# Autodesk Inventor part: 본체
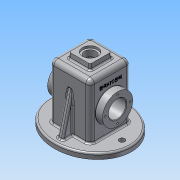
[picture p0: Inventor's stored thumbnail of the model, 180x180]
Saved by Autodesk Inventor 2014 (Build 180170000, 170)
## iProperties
Created: 2017-07
Part Number: 본체
Material: 알루미늄 6061
Document SubType Name: Modeling
Designer: 학생용
Density: 2.71 g/cm^3
Appearance: 알루미늄 - 평지
Mass: 894.559 g
Surface Area: 979.096 cm^2
Volume: 330.096 cm^3
Author: 학생용
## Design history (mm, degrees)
sketch "스케치2"
  geometry: L1 (-75, -65)-(75, -65); L2 (75, -65)-(75, 65); L3 (75, 65)-(-75, 65); L4 (-75, 65)-(-75, -65); L5 (-75, -65)-(75, 65); L6 (75, -65)-(-75, 65); 4 further points; 1 other entity
  constraints: 12 end point, 6 midpoint, 2 horizontal, 2 parallel, 1 perpendicular, 4 other
  dimensions: "d1" = 150 distance of L2.end L3.end; "d2" = 130 distance of L1.end L2.end
extrude "돌출1" new body sketch "스케치2" distance "d3" = 10; taper "d4" = 0 deg
sketch "스케치3"
  geometry: L1 (37, 10)-(-37, 10); L2 (-37, 10)-(-37, 110); L3 (-37, 110)-(37, 110); L4 (37, 110)-(37, 10); L5 (75, 10)-(-75, 10) reference; 2 further points
  constraints: 8 end point, 2 parallel, 1 collinear, 1 horizontal, 1 midpoint, 1 perpendicular, 1 vertical alignment
  dimensions: "d5" = 74 distance of L2.end L3.end; "d6" = 110 distance from line of L3 point (0, 0)
extrude "돌출2" join sketch "스케치3" stored distance "d7" = 74; taper "d8" = 0 deg
fillet "모깎기1" dims "d9" = 8
fillet "모깎기2" dims "d10" = 8
feature "쉘1" dims "d11" = 10, "d12" = 5
sketch "스케치4"
  geometry: L1 (-75, 0)-(-75, 10) reference; L2 (-75, 10)-(-37, 10) reference; L3 (-37, 10)-(-37, 102) reference; L4 (-29, 110)-(29, 110) reference; L5 (37, 102)-(37, 10) reference; L6 (37, 10)-(75, 10) reference; L7 (75, 10)-(75, 0) reference; L8 (75, 0)-(32, 0) reference; L9 (32, 0)-(32, 102) reference; L10 (29, 105)-(-29, 105) reference; L11 (-32, 102)-(-32, 0) reference; L12 (-32, 0)-(-75, 0) reference; L13 (32, 82.5)-(25, 75.5); L14 (25, 75.5)-(25, 55); L15 (25, 55)-(32, 55); L16 (32, 82.5)-(32, 55); L17 (-29, 0)-(29, 0) reference; A1 r 8 centre (-29, 102) between (-29, 110) and (-37, 102) reference; A2 r 8 centre (29, 102) between (37, 102) and (29, 110) reference; A3 r 3 centre (29, 102) between (32, 102) and (29, 105) reference; A4 r 3 centre (-29, 102) between (-29, 105) and (-32, 102) reference; 1 further point
  constraints: 8 end point, 2 perpendicular, 2 point on line, 1 collinear
  dimensions: "d13" = 55 distance between parallel lines of L17 L15; "d14" = 55 diameter of L13.start L15; "d15" = 7 distance between parallel lines of L14 L16; "d16" = 135 deg angle of L9 L13
revolve "회전1" sketch "스케치4" stored, may be unused: angle "d17" = 90 deg
node "작업 평면1"
sketch "스케치5"
  geometry: C1 r 27.5 at (0, 55); 1 further point
  constraints: 1 centre point, 1 vertical alignment
  dimensions: "d19" = 55 distance of point (0, 0) C1.centre; "d20" = 55 diameter of C1
extrude "돌출3" join sketch "스케치5" stored distance "d21" = 74; taper "d22" = 0 deg
node "작업 평면2"
sketch "스케치6"
  geometry: L1 (-20, -20)-(20, -20); L2 (20, -20)-(20, 20); L3 (20, 20)-(-20, 20); L4 (-20, 20)-(-20, -20); L5 (-20, -20)-(20, 20); L6 (20, -20)-(-20, 20); 1 further point
  constraints: 12 end point, 2 midpoint, 2 parallel, 1 horizontal, 1 perpendicular
  dimensions: "d24" = 40 distance of L2.end L3.end; "d25" = 40 distance of L1.end L2.end
extrude "돌출4" join sketch "스케치6" stored distance "d26" = 74; taper "d27" = 0 deg
feature "면 기울기1" dims angle "d28" = 5 deg
sketch "스케치7"
  geometry: 2 further points
  constraints: 1 coincident
hole "구멍1" sketch "스케치7" at (0, 0) diameter "d29" = 21; stored, may be unused: countersink angle "d33" = 90 deg, drill point angle "d35" = 118 deg; dims "d30" = 6, "d31" = 28, "d32" = 4, "d34" = 8
sketch "스케치8"
  geometry: L1 (-65, 0)-(-65, 10) reference; L2 (-65, 10)-(-37, 10) reference; L3 (-37, 10)-(-37, 102) reference; L4 (-29, 110)-(-20, 110) reference; L5 (-20, 110)-(-19.125, 120) reference; L6 (-19.125, 120)-(-14, 120) reference; L7 (-14, 120)-(-14, 116) reference; L8 (-14, 116)-(-10.5, 116) reference; L9 (-10.5, 116)-(-10.5, 105) reference; L10 (-10.5, 105)-(-29, 105) reference; L11 (-32, 102)-(-32, 0) reference; L12 (-32, 0)-(-65, 0) reference; L13 (65, 10)-(65, 0) reference; L14 (65, 0)-(32, 0) reference; L15 (32, 0)-(32, 102) reference; L16 (29, 105)-(10.5, 105) reference; L17 (10.5, 105)-(10.5, 116) reference; L18 (10.5, 116)-(14, 116) reference; L19 (14, 116)-(14, 120) reference; L20 (14, 120)-(19.125, 120) reference; L21 (19.125, 120)-(20, 110) reference; L22 (20, 110)-(29, 110) reference; L23 (37, 102)-(37, 10) reference; L24 (37, 10)-(65, 10) reference; L25 (-55, 10)-(-37, 82.194); A1 r 8 centre (-29, 102) between (-29, 110) and (-37, 102) reference; A2 r 3 centre (-29, 102) between (-29, 105) and (-32, 102) reference; A3 r 3 centre (29, 102) between (32, 102) and (29, 105) reference; A4 r 8 centre (29, 102) between (37, 102) and (29, 110) reference; 1 further point
  constraints: 2 end point, 2 point on line
  dimensions: "d36" = 10 distance from line of L1 L25.start; "d37" = 14 deg angle of L25 L1
feature "리브1" sketch "스케치8" dims "d38" = 1, "d39" = 10, "d40" = 0, "d41" = 0, "d42" = 1, "d43" = 1
hole "구멍2" diameter "d46" = 32; stored, may be unused: countersink angle "d50" = 90 deg, drill point angle "d52" = 118 deg; dims "d44" = 10, "d45" = 10, "d47" = 6, "d48" = 28, "d49" = 4, "d51" = 8
sketch "스케치9"
  geometry: 2 further points
  constraints: 1 horizontal alignment
  dimensions: "d53" = 58 distance of point (58, 0) point (0, 0)
hole "구멍3" sketch "스케치9" at (58, 0) diameter "d54" = 10; stored, may be unused: countersink angle "d58" = 90 deg, drill point angle "d60" = 118 deg; dims "d55" = 6, "d56" = 28, "d57" = 4, "d59" = 8
sketch "스케치10"
  geometry: L1 (-110, 9.875)-(-110, 48.125) reference; L2 (-92, -8)-(0, -8) reference; L3 (0, 66)-(-92, 66) reference; 2 further points
  constraints: 1 other
  dimensions: "d64" = 30 distance from line of L1 point (-80, 29); "d92" = 37 distance from line of point (-80, 29) L3
feature "엠보싱1" sketch "스케치10" dims "d66" = 0.5, "d67" = 0
fillet "모깎기3" dims "d68" = 0.5
fillet "모깎기4" dims "d69" = 0.5
fillet "모깎기7" dims "d72" = 3
fillet "모깎기8" dims "d73" = 3
fillet "모깎기9" dims "d74" = 3
fillet "모깎기10" dims "d75" = 3
fillet "모깎기11" dims "d76" = 3
chamfer "모따기1" distance "d77" = 1; stored, may be unused: second distance "d78" = 2, angle "d79" = 45 deg
fillet "모깎기12" dims "d80" = 3
sketch "스케치11"
  geometry: C1 r 27.5 at (0, 0) reference; 2 further points
  constraints: 1 horizontal alignment
  dimensions: "d81" = 22.5 distance of C1.centre point (-22.5, 0)
hole "구멍4" sketch "스케치11" at (-22.5, 0) diameter "d82" = 3.242; stored, may be unused: countersink angle "d86" = 90 deg, drill point angle "d88" = 118 deg; dims "d83" = 8, "d84" = 4, "d85" = 2, "d87" = 10
node "솔리드1"
mirror "대칭1"
mirror "대칭2"
pattern_linear "직사각형 패턴1" dims "d63" = 116
pattern_circular "원형 패턴1" dims angle "d90" = 360 deg
mirror "대칭3"
node "절단 모서리 투영1"
node "절단 모서리 투영2"
